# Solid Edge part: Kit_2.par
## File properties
Author: bmolnar
Last saved by: bmolnar
Revision: 77
Sűrűség: 0,000 kg/m^3
Pontosság: 0,990
Username: bmolnar
Dokumentum tartalom típus: 0
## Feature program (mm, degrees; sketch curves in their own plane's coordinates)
base feature "unnamed BaseFeature 1"
sketch for "unnamed Hole 1" plane through (-28.25, -28.25, 94) normal (0, 0, 1) x-axis (0, 1, 0)
  hole centre (0, 0) bore radius 3.3235
hole "unnamed Hole 1" through
sketch for "unnamed Hole 2" plane through (-28.25, -28.25, 94) normal (0, 0, 1) x-axis (0, 1, 0)
  hole centre (56.5, 0) bore radius 3.3235
hole "unnamed Hole 2" through
sketch for "unnamed Hole 3" plane through (-28.25, -28.25, 94) normal (0, 0, 1) x-axis (0, 1, 0)
  hole centre (56.5, -56.5) bore radius 3.3235
hole "unnamed Hole 3" through
sketch for "unnamed Hole 4" plane through (-28.25, -28.25, 94) normal (0, 0, 1) x-axis (0, 1, 0)
  hole centre (0, -56.5) bore radius 3.3235
hole "unnamed Hole 4" through
pattern "unnamed Pattern 1" of "unnamed Hole 1", "unnamed Hole 2", "unnamed Hole 3", "unnamed Hole 4"
sketch for "Furat_5" plane through (-38.5, 0, 123.75) normal (1, 0, 0) x-axis (0, 1, 0)
  hole centre (0, -32.25) bore radius 4.283
hole "Furat_5" nominal diameter 9.728 finite  ThreadDepth = 10 mm
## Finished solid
Body 1: solid body, 308 faces, 750 edges, 456 vertices.
  Faces by surface: plane 141, cylinder 75, swept 61, cone 20, torus 10, spline 1
  Edges by curve: line 431, circle 154, spline 126, ellipse 30, curve on surface 9
Bounding box of the edges (mm; curved faces can reach further): 77.000 x 77.000 x 13.750, from (-38.5, -38.5, 85.25) to (38.5, 38.5, 99).
Cylindrical faces by radius (mm): R0.2 x48, R0.2008 x2, R0.2009 x2, R0.402 x1, R0.4899 x1, R3.3235 x4, R4.283 x1, R4.9 x4, R5.15 x4, R5.25 x4, R8.27 x1, R8.85 x1, R9 x1, R10.25 x1
Conical faces (half-angle, radius in mm at the cone's reference point): 0.5 deg R12 x4, 0.5 deg R13.5 x2, 7 deg R9.5925 x1, 14 deg R8.135 x1, 14 deg R8.4811 x1, 17 deg R8.135 x1, 23 deg R8.829 x1, 42.5 deg R8.1233 x1, 45 deg R3.6735 x4, 45 deg R9 x1, 84 deg R8.4608 x1, 85 deg R9.9463 x1, 87 deg R8.1765 x1
Toroidal faces (ring radius, tube radius in mm): R4.7 r0.2 x8, R8.8057 r0.2025 x1, R9.2522 r0.2925 x1
Planar faces by outward normal: +x 12, +y 13, +z 19, -x 15, -y 14, -z 1, oblique 67
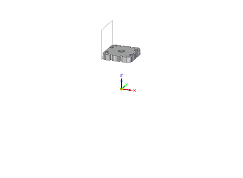
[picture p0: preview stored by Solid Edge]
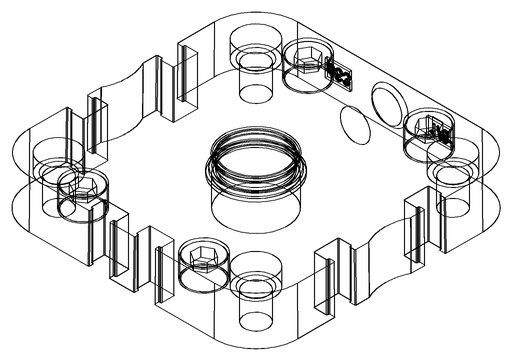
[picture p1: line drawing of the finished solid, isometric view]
